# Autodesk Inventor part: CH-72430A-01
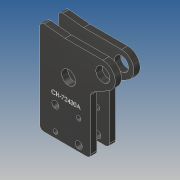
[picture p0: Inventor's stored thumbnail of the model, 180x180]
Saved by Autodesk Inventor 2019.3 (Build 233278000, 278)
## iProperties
Created: 2012-10
Part Number: CH-72430A-01
Material: Ogólny
Document SubType Name: Modeling
Designer: CADENGINEERING4
Density: 1 g/cm^3
Appearance: Ciemnoszara
Author: CADENGINEERING4
Revision Number: ÈÎºÎ
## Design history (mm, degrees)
feature "¾µÏò1"
feature "ÇÐ³ý-À­Éì1"
node "Bryła1"
node "Bryła22"
node "Bryła23"
